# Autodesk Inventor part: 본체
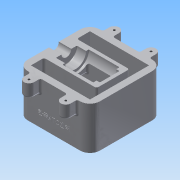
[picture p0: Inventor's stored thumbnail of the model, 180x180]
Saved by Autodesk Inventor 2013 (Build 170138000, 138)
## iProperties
Created: 2018-01
Part Number: 본체
Material: 알루미늄 6061
Document SubType Name: Modeling
Designer: Administrator
Density: 1 g/cm^3
Mass: 367.227 g
Surface Area: 841.146 cm^2
Volume: 367.227 cm^3
Author: Administrator
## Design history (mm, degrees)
sketch "스케치1"
  geometry: L1 (-55, -55)-(55, -55); L2 (55, -55)-(55, 55); L3 (55, 55)-(-55, 55); L4 (-55, 55)-(-55, -55); L5 (-55, -55)-(55, 55); L6 (55, -55)-(-55, 55); 1 further point
  constraints: 12 end point, 2 midpoint, 2 parallel, 1 horizontal, 1 perpendicular
  dimensions: "d0" = 110 distance of L3.end L2.end; "d1" = 110 distance of L2.end L1.end
extrude "돌출1" new body sketch "스케치1" distance "d2" = 65; taper "d3" = 0 deg
sketch "스케치2"
  geometry: L1 (55, 55)-(-55, 55) reference; L2 (-55, 55)-(-55, -55) reference; L3 (-55, -55)-(55, -55) reference; L4 (55, -55)-(55, 55) reference; L5 (55, 55)-(-55, 55) reference; L6 (-55, 55)-(-55, -55) reference; L7 (-55, 65)-(-1, 65); L8 (0, 55)-(0, 82.345); L9 (-35.5, 65)-(-35.5, 55); L10 (-20.5, 65)-(-20.5, 55); L11 (-35.5, 55)-(-20.5, 55); L12 (20.5, 65)-(20.5, 55); L13 (35.5, 55)-(20.5, 55); L14 (35.5, 65)-(35.5, 55); A1 r 7.5 centre (-28, 65) between (-20.5, 65) and (-35.5, 65); A2 r 7.5 centre (28, 65) between (35.5, 65) and (20.5, 65); 3 further points
  constraints: 16 end point, 5 symmetric about line, 4 midpoint, 4 point on circle, 4 point on line, 3 perpendicular, 2 centre point, 2 tangent, 1 coincident, 1 collinear, 1 horizontal alignment, 1 parallel, 1 other
  dimensions: "d5" = 7.5 radius of A1; "d6" = 27 distance from line of L2 A1.centre; "d7" = 10 distance from line of L1 A2.centre
extrude "돌출2" join sketch "스케치2" distance "d8" = 20; taper "d9" = 0 deg
sketch "스케치3"
  geometry: A1 r 7.5 centre (-28, -65) between (-35.5, -65) and (-20.5, -65) reference; A2 r 7.5 centre (28, -65) between (20.5, -65) and (35.5, -65) reference; A3 r 7.5 centre (28, 65) between (35.5, 65) and (20.5, 65) reference; A4 r 7.5 centre (-28, 65) between (-20.5, 65) and (-35.5, 65) reference; 5 further points
  constraints: 4 coincident
hole "구멍1" sketch "스케치3" at (-28, 65), (28, 65), (28, -65), (-28, -65) diameter "d10" = 3.242; stored, may be unused: countersink angle "d14" = 90 deg, drill point angle "d16" = 118 deg; dims "d11" = 9, "d12" = 4, "d13" = 2, "d15" = 11
sketch "스케치4"
  geometry: L1 (55, -55)-(55, 55) reference; L2 (20.5, 55)-(-20.5, 55) reference; L3 (-55, -55)-(-35.5, -55) reference; L4 (-35.5, -55)-(-35.5, -65) reference; L5 (-20.5, -65)-(-20.5, -55) reference; L6 (-20.5, -55)-(20.5, -55) reference; L7 (20.5, -65)-(20.5, -55) reference; L8 (35.5, -55)-(35.5, -65) reference; L9 (35.5, -55)-(55, -55) reference; L10 (55, -55)-(55, 55) reference; L11 (55, 55)-(35.5, 55) reference; L12 (35.5, 55)-(35.5, 65) reference; L13 (20.5, 65)-(20.5, 55) reference; L14 (20.5, 55)-(-20.5, 55) reference; L15 (-20.5, 65)-(-20.5, 55) reference; L16 (-35.5, 55)-(-35.5, 65) reference; L17 (-35.5, 55)-(-55, 55) reference; L18 (-55, 55)-(-55, -55) reference; L19 (-45, -45)-(45, -45); L20 (45, -45)-(45, 45); L21 (45, 45)-(-45, 45); L22 (-45, -45)-(45, 45); L23 (45, -45)-(-45, 45); L24 (-45, 25)-(35, 25); L25 (35, 25)-(35, -25); L26 (35, -25)-(-45, -25); L27 (-45, 45)-(-45, 25); L28 (-45, -25)-(-45, -45); C1 r 1.621 at (28, -65) reference; C2 r 1.621 at (-28, 65) reference; C3 r 1.621 at (28, 65) reference; C4 r 1.621 at (-28, -65) reference; A1 r 7.5 centre (-28, -65) between (-35.5, -65) and (-20.5, -65) reference; A2 r 7.5 centre (28, -65) between (20.5, -65) and (35.5, -65) reference; A3 r 7.5 centre (28, 65) between (35.5, 65) and (20.5, 65) reference; A4 r 7.5 centre (-28, 65) between (-20.5, 65) and (-35.5, 65) reference; 1 further point
  constraints: 20 end point, 4 parallel, 2 horizontal, 2 midpoint, 2 perpendicular
  dimensions: "d17" = 90 distance of L21.end L20.end; "d18" = 90 distance of L20.end L19.end; "d19" = 30 distance between parallel lines of L24 L2; "d20" = 20 distance between parallel lines of L25 L1; "d22" = 20 distance between parallel lines of L24 L21; "d28" = 30 distance between parallel lines of L6 L26
extrude "돌출3" cut sketch "스케치4" stored distance "d23" = 20; taper "d24" = 0 deg
sketch "스케치5"
  geometry: L1 (65, 110)-(65, 0) reference; C1 r 7.5 at (65, 55); 1 further point
  constraints: 1 centre point, 1 midpoint
  dimensions: "d25" = 15 diameter of C1
extrude "돌출4" cut sketch "스케치5" distance "d26" = 85; taper "d27" = 0 deg
node "작업 평면2"
  node "작업 평면1"
sketch "스케치6"
  geometry: C1 r 16 at (0, 65); A1 r 7.5 centre (0, 65) between (-7.5, 65) and (7.5, 65) reference; 1 further point
  constraints: 1 centre point, 1 coincident
  dimensions: "d31" = 32 diameter of C1
extrude "돌출5" cut sketch "스케치6" distance "d32" = 61; taper "d33" = 0 deg
node "작업 평면3"
sketch "스케치7"
  geometry: C1 r 20 at (0, 65); A1 r 16 centre (0, 65) between (-16, 65) and (16, 65) reference; 1 further point
  constraints: 1 centre point, 1 coincident
  dimensions: "d35" = 40 diameter of C1
extrude "돌출6" cut sketch "스케치7" distance "d36" = 47; taper "d37" = 0 deg
node "작업 평면4"
sketch "스케치8"
  geometry: C1 r 15 at (65, 0); A1 r 7.5 centre (65, 0) between (65, 7.5) and (65, -7.5) reference; 1 further point
  constraints: 1 centre point, 1 coincident
  dimensions: "d39" = 30 diameter of C1
extrude "돌출7" cut sketch "스케치8" distance "d40" = 5; taper "d41" = 0 deg
node "작업 평면5"
sketch "스케치14"
  geometry: L1 (-18.5, 15)-(18.5, 15); L2 (18.5, 15)-(18.5, -15); L3 (18.5, -15)-(-18.5, -15); L4 (-18.5, -15)-(-18.5, 15); 3 further points
  constraints: 8 end point, 2 midpoint, 2 parallel, 1 horizontal, 1 horizontal alignment, 1 perpendicular, 1 vertical alignment
  dimensions: "d64" = 37 distance of L1.start L1.end; "d66" = 30 distance of L1.end L2.end
extrude "돌출11" cut sketch "스케치14" distance "d67" = 35; taper "d68" = 0 deg
sketch "스케치15"
  geometry: L1 (45, 0)-(-35, 0) reference; L2 (-35, 65)-(-35, 0) reference; L3 (45, 65)-(45, 0) reference; L4 (-35, 30)-(45, 8.564); L5 (45, 8.564)-(45, 0); L6 (-35, 0)-(45, 0); L7 (-35, 30)-(-35, 0); 1 further point
  constraints: 8 end point, 2 perpendicular, 2 point on line, 1 collinear
  dimensions: "d69" = 30 distance from line of L1 L4.start; "d70" = 105 deg angle of L3 L4
extrude "돌출12" cut sketch "스케치15" stored distance "d71" = 55; taper "d72" = 0 deg
sketch "스케치16"
  geometry: L1 (-35, 30)-(45, 8.564) reference; L2 (55, 0)-(55, 65) reference; L3 (-15.681, 30)-(55, 11.061); L4 (18.5, 30)-(-18.5, 30) reference; L5 (18.5, 38.841)-(55, 29.061); L6 (18.5, 51.771)-(18.5, 30) reference; L7 (18.5, 38.841)-(-15.681, 30); L8 (55, 29.061)-(55, 11.061); 1 further point
  constraints: 8 end point, 4 point on line, 2 parallel, 1 collinear
  dimensions: "d73" = 5 distance between parallel lines of L1 L3; "d74" = 18 distance of L3.end L5.end
extrude "돌출13" cut sketch "스케치16" stored distance "d75" = 30; taper "d76" = 0 deg
fillet "모깎기1" dims "d80" = 15
fillet "모깎기2" dims "d81" = 3
fillet "모깎기3" dims "d82" = 3
fillet "모깎기4" dims "d83" = 3
fillet "모깎기5" dims "d84" = 3
sketch "스케치17"
  geometry: L1 (0, 0)-(80, 0) reference; L2 (-15, 65)-(-15, 0) reference; 2 further points
  constraints: 1 other
  dimensions: "d86" = 20 distance from line of point (40, 20) L1; "d87" = 55 distance from line of point (40, 20) L2
feature "엠보싱1" sketch "스케치17" dims "d0" = 110, "d1" = 110, "d5" = 7.5, "d6" = 27, "d7" = 10, "d88" = 0.5, "d89" = 0
fillet "모깎기7" dims "d90" = 1
fillet "모깎기8" dims "d91" = 3
node "솔리드1"
mirror "대칭1"
node "투영된 루프1"
node "투영된 루프2"
other parameters: "d29" = -55, "d30" = 19, "d34" = 14, "d38" = 65, "d63" = 65
